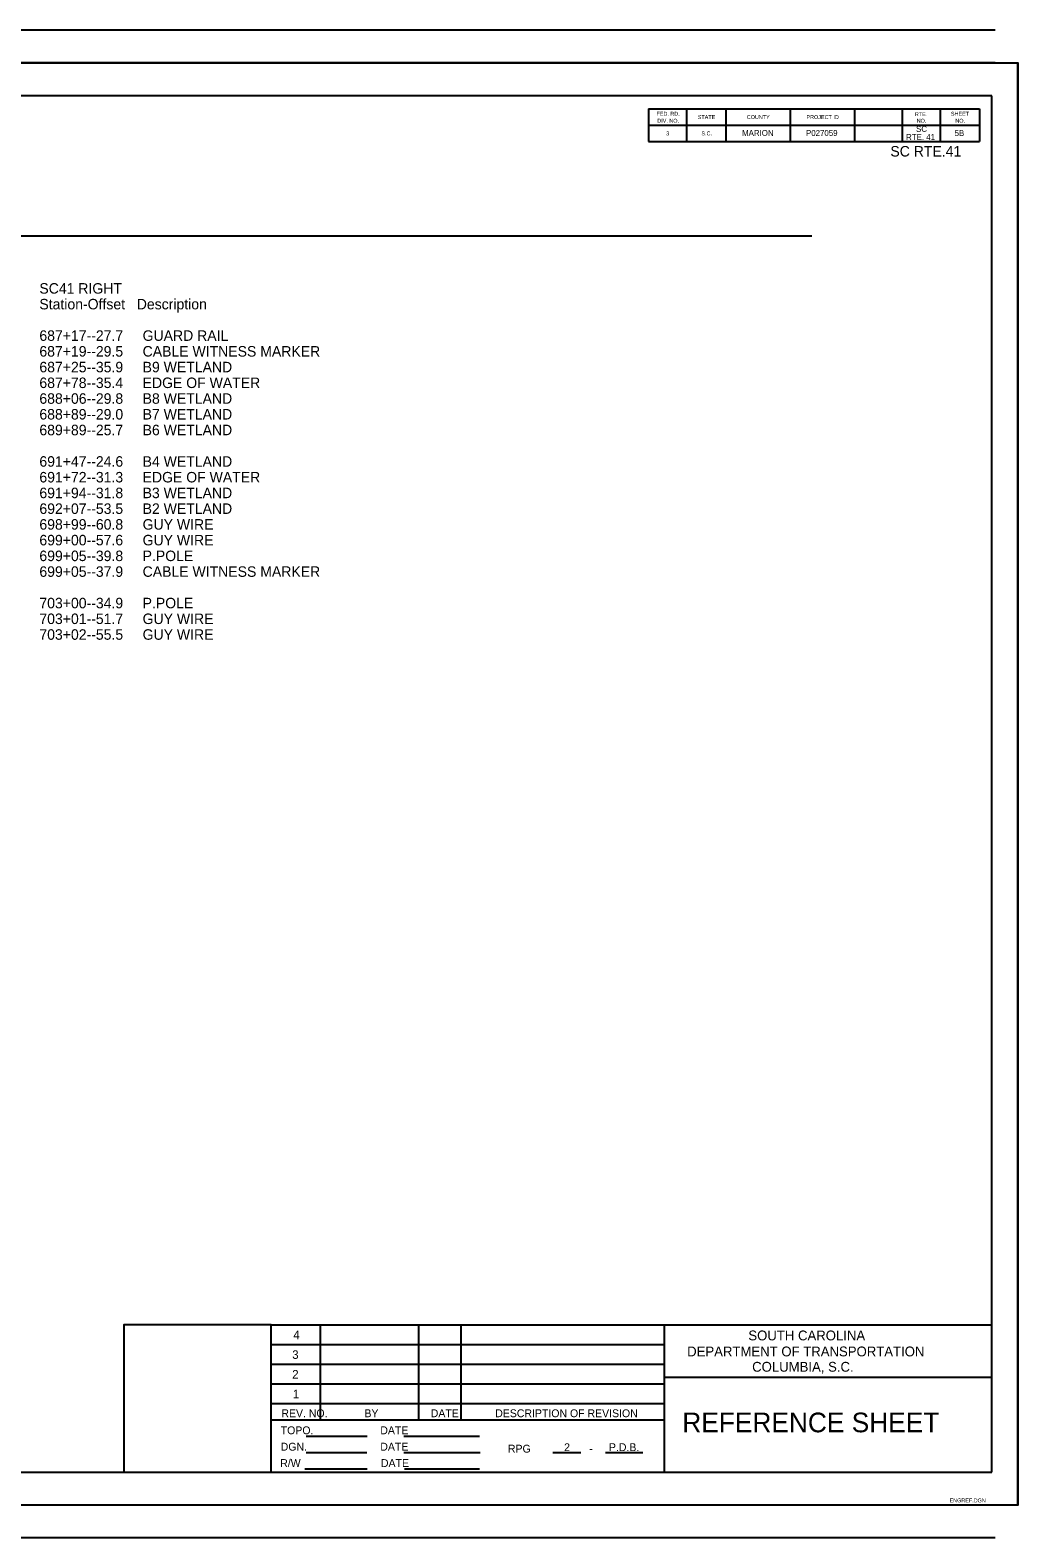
# Model space of a CAD drawing. Extents: x -13615 to 47191, y -1934 to 4415.
# Drawn here: x -9321 to -8567, y 2072 to 3222 of the extents above; entities that cross this region are included whole.
import ezdxf

# ---------------------------------------------------------------- set-up
doc = ezdxf.new("R2010")
doc.units = 0
for name, color, linetype in [('RD_PD_Final_TX', 7, 'Continuous'), ('RD_SHT_Bndy', 7, 'Continuous'), ('RD_SHT_IplotShp', 7, 'Continuous'), ('RD_SHT_TX', 7, 'Continuous'), ('RD_TX_StaOff', 7, 'Continuous'), ('RD_TX_TitleSht', 7, 'Continuous')]:
    doc.layers.add(name, color=color, linetype=linetype)

msp = doc.modelspace()

# ---------------------------------------------------------------- linework, layer by layer
at = {"layer": 'RD_SHT_Bndy'}
for p, q in [((-8584.1, 3221.6), (-10344.1, 3221.6)), ((-8584.1, 3196.6), (-10344.1, 3196.6)), ((-8586.5, 3171.6), (-10261.5, 3171.6)), ((-8586.5, 2121.6), (-8586.5, 3171.6)), ((-8848.5, 3161.6), (-8848.5, 3136.6)), ((-8848.5, 3161.6), (-8596, 3161.6)), ((-8819.5, 3161.6), (-8819.5, 3136.6)), ((-8789.5, 3161.6), (-8789.5, 3136.6)), ((-8740.5, 3161.6), (-8740.5, 3136.6)), ((-8691.5, 3161.6), (-8691.5, 3136.6)), ((-8655, 3161.6), (-8655, 3136.6)), ((-8626, 3161.6), (-8626, 3136.6)), ((-8596, 3161.6), (-8596, 3136.6)), ((-8848.5, 3149.1), (-8596, 3149.1)), ((-8848.5, 3136.6), (-8596, 3136.6)), ((-10124, 3064.6), (-8724, 3064.6)), ((-9136.5, 2121.6), (-9136.5, 2234.1)), ((-9136.5, 2234.1), (-8586.9, 2234.1)), ((-9099, 2161.4), (-9099, 2234)), ((-9024, 2161.6), (-9024, 2234)), ((-8991.5, 2161.6), (-8991.5, 2234)), ((-8836.5, 2121.4), (-8836.5, 2234)), ((-9136.5, 2219.1), (-8836.5, 2219.1)), ((-9136.5, 2204.1), (-8836.5, 2204.1)), ((-9136.5, 2189.1), (-8836.5, 2189.1)), ((-8836.5, 2194.1), (-8586.9, 2194.1)), ((-9136.5, 2174.1), (-8836.5, 2174.1)), ((-9136.5, 2161.6), (-8836.5, 2161.6)), ((-9110, 2149.1), (-9063.3, 2149.1)), ((-9035.3, 2149.1), (-8977.7, 2149.1)), ((-9110, 2136.6), (-9063.7, 2136.6)), ((-9035.3, 2136.6), (-8977.2, 2136.6)), ((-8921.6, 2136.6), (-8900.2, 2136.6)), ((-8881.4, 2136.6), (-8853, 2136.6)), ((-10261.5, 2121.6), (-8586.5, 2121.6)), ((-9110.9, 2124.1), (-9063.3, 2124.1)), ((-9034.9, 2124.1), (-8977.7, 2124.1)), ((-8584.1, 2096.6), (-10344.1, 2096.6)), ((-8584.1, 2071.6), (-10344.1, 2071.6))]:
    msp.add_line(p, q, dxfattribs=at)
msp.add_lwpolyline([(-9136.5, 2234.1), (-9249, 2234.1), (-9249, 2121.6)], dxfattribs=at)
at = {"layer": 'RD_SHT_IplotShp'}
msp.add_lwpolyline([(-10362.7, 3196.6), (-8566.7, 3196.6), (-8566.7, 2096.6), (-10362.7, 2096.6)], close=True, dxfattribs=at)
at = {"layer": 'RD_SHT_TX'}
msp.add_line((-8566.7, 2096.6), (-8566.7, 3196.6), dxfattribs=at)

# ---------------------------------------------------------------- texts
at = {"layer": 'RD_PD_Final_TX'}
for s, p in [('MARION', (-8777.2, 3140.9)), ('P027059', (-8728.4, 3140.9)), ('RTE. 41', (-8652, 3137.8)), ('SC ', (-8644.4, 3144))]:
    msp.add_text(s, height=4.5, rotation=360, dxfattribs=at).set_placement(p)
for s, height, p in [('5B', 4.5, (-8615, 3140.8)), ('2', 6, (-8913, 2137.7)), ('P.D.B.', 6, (-8878.8, 2137.7))]:
    msp.add_text(s, height=height, dxfattribs=at).set_placement(p)
at = {"layer": 'RD_SHT_Bndy'}
msp.add_text('-', height=6, dxfattribs=at).set_placement((-8893.9, 2136.6))
at = {"layer": 'RD_SHT_TX'}
for s, height, p in [('FED. RD.', 3, (-8842.5, 3156.3)), ('DIV. NO.', 3, (-8841.9, 3151)), ('STATE', 3, (-8811, 3153.8)), ('COUNTY', 3, (-8773.6, 3153.8)), ('PROJECT ID', 3, (-8728, 3153.8)), ('NO.', 3, (-8643.9, 3151)), ('SHEET', 3, (-8617.8, 3156.3)), ('NO.', 3, (-8614.4, 3151)), ('3', 3, (-8835.1, 3141.3)), ('S.C.', 3, (-8808.2, 3141.3)), ('4', 6.5, (-9119.7, 2223.1)), ('SOUTH CAROLINA', 7.5, (-8772.4, 2222.2)), ('3', 6.5, (-9120.5, 2208.1)), ('DEPARTMENT OF TRANSPORTATION', 7.5, (-8819.1, 2210)), ('2', 6.5, (-9120.5, 2193.1)), ('COLUMBIA, S.C.', 7.5, (-8769.5, 2198.3)), ('1', 6.5, (-9120.1, 2178.1)), ('REV. NO.', 6, (-9128.8, 2163.6)), ('BY', 6, (-9065.4, 2163.6)), ('DATE', 6, (-9014.8, 2163.6)), ('DESCRIPTION OF REVISION', 6, (-8965.6, 2163.6)), ('REFERENCE SHEET', 15, (-8822.8, 2152.1)), ('TOPO.', 6, (-9129.3, 2150.6)), ('DATE', 6, (-9053.3, 2150.6)), ('DGN.', 6, (-9129.3, 2138.1)), ('DATE', 6, (-9053.3, 2138.1)), ('RPG', 6, (-8955.9, 2136.6)), ('R/W', 6, (-9129.7, 2125.6)), ('DATE', 6, (-9052.8, 2125.6)), ('ENGREF.DGN', 3, (-8618.8, 2098.6))]:
    msp.add_text(s, height=height, dxfattribs=at).set_placement(p)
at = {"layer": 'RD_TX_StaOff'}
for s, p in [('SC41 RIGHT', (-9313.5, 3020.6)), ('Station-Offset   Description', (-9313.5, 3008.6)), ('687+17--27.7     GUARD RAIL', (-9313.5, 2984.6)), ('687+19--29.5     CABLE WITNESS MARKER', (-9313.5, 2972.6)), ('687+25--35.9     B9 WETLAND', (-9313.5, 2960.6)), ('687+78--35.4     EDGE OF WATER', (-9313.5, 2948.6)), ('688+06--29.8     B8 WETLAND', (-9313.5, 2936.6)), ('688+89--29.0     B7 WETLAND', (-9313.5, 2924.6)), ('689+89--25.7     B6 WETLAND', (-9313.5, 2912.6)), ('691+47--24.6     B4 WETLAND', (-9313.5, 2888.6)), ('691+72--31.3     EDGE OF WATER', (-9313.5, 2876.6)), ('691+94--31.8     B3 WETLAND', (-9313.5, 2864.6)), ('692+07--53.5     B2 WETLAND', (-9313.5, 2852.6)), ('698+99--60.8     GUY WIRE', (-9313.5, 2840.6)), ('699+00--57.6     GUY WIRE', (-9313.5, 2828.6)), ('699+05--39.8     P.POLE', (-9313.5, 2816.6)), ('699+05--37.9     CABLE WITNESS MARKER', (-9313.5, 2804.6)), ('703+00--34.9     P.POLE', (-9313.5, 2780.6)), ('703+01--51.7     GUY WIRE', (-9313.5, 2768.6)), ('703+02--55.5     GUY WIRE', (-9313.5, 2756.6))]:
    msp.add_text(s, height=8, dxfattribs=at).set_placement(p)
at = {"layer": 'RD_TX_TitleSht'}
for s, height, p in [('RTE.', 3, (-8645.3, 3156)), ('SC RTE.41', 8, (-8664, 3125.2))]:
    msp.add_text(s, height=height, dxfattribs=at).set_placement(p)

doc.saveas('drawing.dxf')
